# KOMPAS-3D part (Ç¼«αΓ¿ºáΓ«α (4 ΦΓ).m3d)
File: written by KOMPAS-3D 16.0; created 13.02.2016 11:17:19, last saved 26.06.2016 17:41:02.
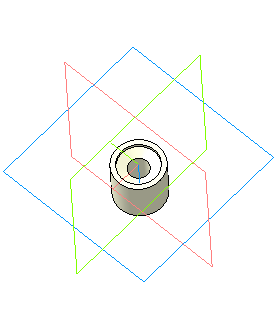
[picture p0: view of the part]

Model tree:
1. Эскиз:1
2. Операция выдавливания:1
     Расстояние 1 = 16
3. Фаска:1
     Угол = 45; Длина 1 = 2; Длина 2 = 2
4. Эскиз:2
5. Вырезать элемент выдавливания:1
     Расстояние 1 = 1
6. Эскиз:3
7. Вырезать элемент выдавливания:2
     Расстояние 1 = 14
8. Уклон:1
     Угол уклона = 1
9. Фаска:5
     Угол = 73; Длина 1 = 1.0001; Длина 2 = 3.27118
